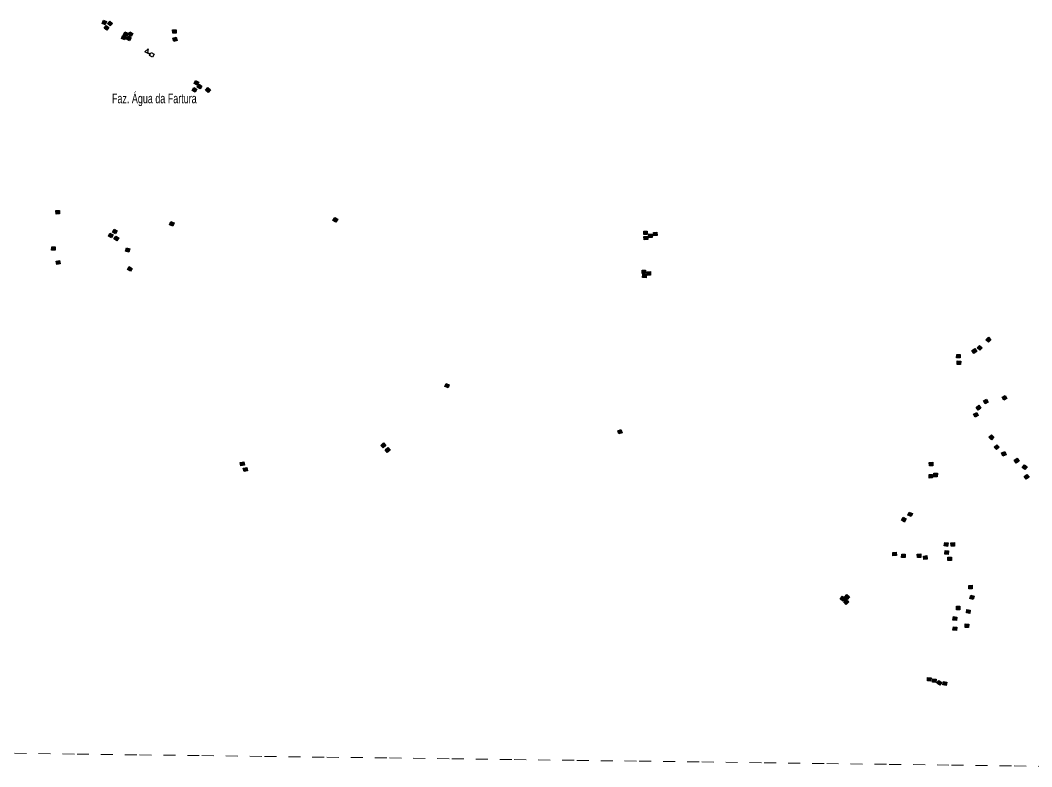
# Model space of a CAD drawing. Extents: x 679 to 705, y 7427.4 to 7455.4.
# Drawn here: x 683.78 to 692.24, y 7427.52 to 7433.76 of the extents above; entities that cross this region are included whole.
import ezdxf

# ---------------------------------------------------------------- set-up
doc = ezdxf.new("R2010")
doc.units = 0
doc.header["$LTSCALE"] = 0.032
doc.linetypes.add('SHORT_DASHED', pattern=[2.7, 1.5, -1.2])
for name, color, linetype, lineweight in [('2', 7, 'Continuous', 25), ('4', 7, 'Continuous', 25), ('58', 7, 'SHORT_DASHED', 13)]:
    doc.layers.add(name, color=color, linetype=linetype, lineweight=lineweight)
doc.layers.add('61', color=7, linetype='Continuous')

msp = doc.modelspace()

# ---------------------------------------------------------------- hatches: boundary and pattern name
at = {"layer": '2'}
for points in [[(684.5058, 7433.7514), (684.4944, 7433.7248), (684.4678, 7433.7362), (684.4792, 7433.7628)], [(684.5551, 7433.7368), (684.5357, 7433.7153), (684.5141, 7433.7347), (684.5335, 7433.7562)], [(684.5253, 7433.7023), (684.5082, 7433.6788), (684.4848, 7433.6959), (684.5019, 7433.7193)], [(684.6858, 7433.6543), (684.6741, 7433.6277), (684.6476, 7433.6393), (684.6592, 7433.6659)], [(684.7242, 7433.6515), (684.7106, 7433.6259), (684.685, 7433.6395), (684.6986, 7433.6651)], [(685.0861, 7433.6838), (685.087, 7433.6548), (685.058, 7433.6539), (685.0571, 7433.6829)], [(684.6678, 7433.6238), (684.6549, 7433.5979), (684.6289, 7433.6109), (684.6419, 7433.6368)], [(684.7103, 7433.6159), (684.6961, 7433.5906), (684.6708, 7433.6049), (684.685, 7433.6301)], [(685.0876, 7433.622), (685.096, 7433.5942), (685.0682, 7433.5859), (685.0598, 7433.6136)], [(685.2755, 7433.2451), (685.2622, 7433.2193), (685.2364, 7433.2326), (685.2497, 7433.2584)], [(685.3027, 7433.2123), (685.2869, 7433.188), (685.2626, 7433.2038), (685.2784, 7433.2281)], [(685.2603, 7433.1851), (685.2458, 7433.1601), (685.2207, 7433.1746), (685.2353, 7433.1997)], [(685.3514, 7433.2006), (685.3729, 7433.1812), (685.3535, 7433.1597), (685.332, 7433.1791)], [(684.1105, 7432.172), (684.1117, 7432.1431), (684.0827, 7432.1419), (684.0816, 7432.1709)], [(685.0432, 7432.08), (685.0697, 7432.0682), (685.0578, 7432.0417), (685.0314, 7432.0535)], [(686.4118, 7432.113), (686.437, 7432.0985), (686.4225, 7432.0734), (686.3973, 7432.0879)], [(684.5333, 7431.983), (684.5592, 7431.97), (684.5463, 7431.9441), (684.5203, 7431.9571)], [(684.5681, 7432.0157), (684.5932, 7432.0012), (684.5788, 7431.9761), (684.5536, 7431.9905)], [(684.5833, 7431.9583), (684.6075, 7431.9423), (684.5915, 7431.9181), (684.5673, 7431.9341)], [(689.0243, 7431.9993), (689.0235, 7431.9703), (688.9945, 7431.9712), (688.9953, 7432.0002)], [(689.0254, 7431.9587), (689.0281, 7431.9298), (688.9992, 7431.9271), (688.9965, 7431.956)], [(689.0652, 7431.9753), (689.0641, 7431.9463), (689.0351, 7431.9474), (689.0362, 7431.9764)], [(689.1042, 7431.9909), (689.1066, 7431.962), (689.0777, 7431.9596), (689.0753, 7431.9885)], [(684.0761, 7431.8682), (684.0747, 7431.8393), (684.0457, 7431.8407), (684.0472, 7431.8697)], [(684.6721, 7431.8593), (684.6999, 7431.8511), (684.6917, 7431.8233), (684.6639, 7431.8314)], [(684.1124, 7431.7542), (684.117, 7431.7256), (684.0884, 7431.721), (684.0838, 7431.7496)], [(684.6954, 7431.7038), (684.7199, 7431.6882), (684.7043, 7431.6637), (684.6798, 7431.6793)], [(689.0099, 7431.6735), (689.0099, 7431.6445), (688.9809, 7431.6445), (688.9809, 7431.6735)], [(689.0166, 7431.6372), (689.0142, 7431.6083), (688.9853, 7431.6107), (688.9877, 7431.6396)], [(689.0497, 7431.6617), (689.0516, 7431.6328), (689.0226, 7431.6309), (689.0208, 7431.6598)], [(691.8751, 7431.112), (691.8956, 7431.0914), (691.8751, 7431.0709), (691.8546, 7431.0915)], [(691.8016, 7431.0445), (691.8226, 7431.0245), (691.8026, 7431.0035), (691.7816, 7431.0235)], [(691.6393, 7430.9682), (691.6382, 7430.9392), (691.6093, 7430.9403), (691.6103, 7430.9692)], [(691.7609, 7431.0174), (691.777, 7430.9933), (691.7528, 7430.9772), (691.7368, 7431.0014)], [(691.6435, 7430.9134), (691.6424, 7430.8844), (691.6135, 7430.8855), (691.6145, 7430.9144)], [(687.3428, 7430.7265), (687.3696, 7430.7155), (687.3587, 7430.6887), (687.3318, 7430.6996)], [(692.016, 7430.6257), (692.0293, 7430.5999), (692.0035, 7430.5866), (691.9902, 7430.6124)], [(691.795, 7430.5438), (691.8123, 7430.5206), (691.7891, 7430.5032), (691.7718, 7430.5265)], [(691.8588, 7430.5941), (691.873, 7430.5689), (691.8477, 7430.5546), (691.8335, 7430.5799)], [(691.7771, 7430.4838), (691.7902, 7430.458), (691.7644, 7430.4449), (691.7512, 7430.4707)], [(688.8038, 7430.3414), (688.8143, 7430.3144), (688.7873, 7430.3038), (688.7768, 7430.3308)], [(691.9001, 7430.2963), (691.9206, 7430.2758), (691.9001, 7430.2553), (691.8796, 7430.2758)], [(686.8188, 7430.2286), (686.8386, 7430.2075), (686.8174, 7430.1876), (686.7976, 7430.2088)], [(686.8565, 7430.1904), (686.8743, 7430.1675), (686.8514, 7430.1497), (686.8336, 7430.1726)], [(691.9454, 7430.2138), (691.9649, 7430.1924), (691.9436, 7430.1728), (691.924, 7430.1942)], [(692.0112, 7430.1574), (692.0223, 7430.1306), (691.9955, 7430.1195), (691.9844, 7430.1463)], [(692.1148, 7430.1014), (692.1316, 7430.0778), (692.108, 7430.061), (692.0912, 7430.0846)], [(685.6515, 7430.0709), (685.6569, 7430.0425), (685.6285, 7430.037), (685.623, 7430.0655)], [(685.6764, 7430.0247), (685.6827, 7429.9964), (685.6544, 7429.9901), (685.6481, 7430.0184)], [(691.4092, 7430.0677), (691.4118, 7430.0388), (691.3829, 7430.0362), (691.3803, 7430.0651)], [(692.1755, 7430.0465), (692.1977, 7430.0278), (692.179, 7430.0056), (692.1568, 7430.0243)], [(691.4078, 7429.9654), (691.4089, 7429.9364), (691.3799, 7429.9354), (691.3788, 7429.9643)], [(691.4489, 7429.9752), (691.4481, 7429.9462), (691.4191, 7429.9469), (691.4199, 7429.9759)], [(692.1967, 7429.966), (692.2143, 7429.943), (692.1912, 7429.9254), (692.1736, 7429.9484)], [(691.1626, 7429.6074), (691.1878, 7429.5931), (691.1735, 7429.5678), (691.1483, 7429.5822)], [(691.214, 7429.6513), (691.2403, 7429.6391), (691.2281, 7429.6128), (691.2018, 7429.6251)], [(691.5383, 7429.3931), (691.534, 7429.3644), (691.5053, 7429.3687), (691.5096, 7429.3974)], [(691.5905, 7429.3961), (691.5923, 7429.3672), (691.5634, 7429.3653), (691.5615, 7429.3943)], [(691.1041, 7429.3155), (691.1057, 7429.2866), (691.0767, 7429.285), (691.0752, 7429.314)], [(691.1791, 7429.2999), (691.1788, 7429.2709), (691.1498, 7429.2712), (691.1501, 7429.3002)], [(691.3093, 7429.3008), (691.3109, 7429.2718), (691.2819, 7429.2702), (691.2803, 7429.2991)], [(691.3615, 7429.2865), (691.3644, 7429.2577), (691.3356, 7429.2547), (691.3326, 7429.2835)], [(691.5418, 7429.3263), (691.5393, 7429.2974), (691.5104, 7429.2999), (691.5129, 7429.3288)], [(691.566, 7429.2746), (691.566, 7429.2456), (691.537, 7429.2456), (691.537, 7429.2746)], [(691.7391, 7429.0388), (691.7396, 7429.0098), (691.7106, 7429.0093), (691.7101, 7429.0383)], [(690.6569, 7428.9475), (690.6783, 7428.9279), (690.6587, 7428.9065), (690.6373, 7428.926)], [(690.6874, 7428.92), (690.7079, 7428.8995), (690.6874, 7428.879), (690.6669, 7428.8995)], [(690.692, 7428.9622), (690.7142, 7428.9436), (690.6956, 7428.9213), (690.6734, 7428.94)], [(691.757, 7428.9481), (691.7486, 7428.9203), (691.7208, 7428.9287), (691.7292, 7428.9565)], [(691.6362, 7428.8637), (691.6362, 7428.8347), (691.6072, 7428.8347), (691.6072, 7428.8637)], [(691.7236, 7428.832), (691.7195, 7428.8033), (691.6908, 7428.8074), (691.6949, 7428.8361)], [(691.6113, 7428.773), (691.6077, 7428.7442), (691.5789, 7428.7478), (691.5825, 7428.7766)], [(691.6115, 7428.6882), (691.6074, 7428.6595), (691.5787, 7428.6636), (691.5828, 7428.6923)], [(691.7105, 7428.7151), (691.7099, 7428.6861), (691.6809, 7428.6868), (691.6815, 7428.7158)], [(691.3961, 7428.2656), (691.3936, 7428.2367), (691.3647, 7428.2392), (691.3672, 7428.2681)], [(691.4383, 7428.2551), (691.436, 7428.2262), (691.4071, 7428.2286), (691.4094, 7428.2575)], [(691.4851, 7428.2269), (691.4684, 7428.2032), (691.4447, 7428.2199), (691.4613, 7428.2436)], [(691.5284, 7428.2302), (691.523, 7428.2017), (691.4945, 7428.2072), (691.5, 7428.2357)]]:
    msp.add_hatch(color=256, dxfattribs=at).paths.add_polyline_path(points)

# ---------------------------------------------------------------- linework, layer by layer
for points in [[(684.5058, 7433.7514), (684.4944, 7433.7248), (684.4678, 7433.7362), (684.4792, 7433.7628)], [(684.5551, 7433.7368), (684.5357, 7433.7153), (684.5141, 7433.7347), (684.5335, 7433.7562)], [(684.5253, 7433.7023), (684.5082, 7433.6788), (684.4848, 7433.6959), (684.5019, 7433.7193)], [(684.6858, 7433.6543), (684.6741, 7433.6277), (684.6476, 7433.6393), (684.6592, 7433.6659)], [(684.7242, 7433.6515), (684.7106, 7433.6259), (684.685, 7433.6395), (684.6986, 7433.6651)], [(685.0861, 7433.6838), (685.087, 7433.6548), (685.058, 7433.6539), (685.0571, 7433.6829)], [(684.6678, 7433.6238), (684.6549, 7433.5979), (684.6289, 7433.6109), (684.6419, 7433.6368)], [(684.7103, 7433.6159), (684.6961, 7433.5906), (684.6708, 7433.6049), (684.685, 7433.6301)], [(685.0876, 7433.622), (685.096, 7433.5942), (685.0682, 7433.5859), (685.0598, 7433.6136)], [(685.2755, 7433.2451), (685.2622, 7433.2193), (685.2364, 7433.2326), (685.2497, 7433.2584)], [(685.3027, 7433.2123), (685.2869, 7433.188), (685.2626, 7433.2038), (685.2784, 7433.2281)], [(685.2603, 7433.1851), (685.2458, 7433.1601), (685.2207, 7433.1746), (685.2353, 7433.1997)], [(685.3514, 7433.2006), (685.3729, 7433.1812), (685.3535, 7433.1597), (685.332, 7433.1791)], [(684.1105, 7432.172), (684.1117, 7432.1431), (684.0827, 7432.1419), (684.0816, 7432.1709)], [(685.0432, 7432.08), (685.0697, 7432.0682), (685.0578, 7432.0417), (685.0314, 7432.0535)], [(686.4118, 7432.113), (686.437, 7432.0985), (686.4225, 7432.0734), (686.3973, 7432.0879)], [(684.5333, 7431.983), (684.5592, 7431.97), (684.5463, 7431.9441), (684.5203, 7431.9571)], [(684.5681, 7432.0157), (684.5932, 7432.0012), (684.5788, 7431.9761), (684.5536, 7431.9905)], [(684.5833, 7431.9583), (684.6075, 7431.9423), (684.5915, 7431.9181), (684.5673, 7431.9341)], [(689.0243, 7431.9993), (689.0235, 7431.9703), (688.9945, 7431.9712), (688.9953, 7432.0002)], [(689.0254, 7431.9587), (689.0281, 7431.9298), (688.9992, 7431.9271), (688.9965, 7431.956)], [(689.0652, 7431.9753), (689.0641, 7431.9463), (689.0351, 7431.9474), (689.0362, 7431.9764)], [(689.1042, 7431.9909), (689.1066, 7431.962), (689.0777, 7431.9596), (689.0753, 7431.9885)], [(684.0761, 7431.8682), (684.0747, 7431.8393), (684.0457, 7431.8407), (684.0472, 7431.8697)], [(684.6721, 7431.8593), (684.6999, 7431.8511), (684.6917, 7431.8233), (684.6639, 7431.8314)], [(684.1124, 7431.7542), (684.117, 7431.7256), (684.0884, 7431.721), (684.0838, 7431.7496)], [(684.6954, 7431.7038), (684.7199, 7431.6882), (684.7043, 7431.6637), (684.6798, 7431.6793)], [(689.0099, 7431.6735), (689.0099, 7431.6445), (688.9809, 7431.6445), (688.9809, 7431.6735)], [(689.0166, 7431.6372), (689.0142, 7431.6083), (688.9853, 7431.6107), (688.9877, 7431.6396)], [(689.0497, 7431.6617), (689.0516, 7431.6328), (689.0226, 7431.6309), (689.0208, 7431.6598)], [(691.8751, 7431.112), (691.8956, 7431.0914), (691.8751, 7431.0709), (691.8546, 7431.0915)], [(691.8016, 7431.0445), (691.8226, 7431.0245), (691.8026, 7431.0035), (691.7816, 7431.0235)], [(691.6393, 7430.9682), (691.6382, 7430.9392), (691.6093, 7430.9403), (691.6103, 7430.9692)], [(691.7609, 7431.0174), (691.777, 7430.9933), (691.7528, 7430.9772), (691.7368, 7431.0014)], [(691.6435, 7430.9134), (691.6424, 7430.8844), (691.6135, 7430.8855), (691.6145, 7430.9144)], [(687.3428, 7430.7265), (687.3696, 7430.7155), (687.3587, 7430.6887), (687.3318, 7430.6996)], [(692.016, 7430.6257), (692.0293, 7430.5999), (692.0035, 7430.5866), (691.9902, 7430.6124)], [(691.795, 7430.5438), (691.8123, 7430.5206), (691.7891, 7430.5032), (691.7718, 7430.5265)], [(691.8588, 7430.5941), (691.873, 7430.5689), (691.8477, 7430.5546), (691.8335, 7430.5799)], [(691.7771, 7430.4838), (691.7902, 7430.458), (691.7644, 7430.4449), (691.7512, 7430.4707)], [(688.8038, 7430.3414), (688.8143, 7430.3144), (688.7873, 7430.3038), (688.7768, 7430.3308)], [(691.9001, 7430.2963), (691.9206, 7430.2758), (691.9001, 7430.2553), (691.8796, 7430.2758)], [(686.8188, 7430.2286), (686.8386, 7430.2075), (686.8174, 7430.1876), (686.7976, 7430.2088)], [(686.8565, 7430.1904), (686.8743, 7430.1675), (686.8514, 7430.1497), (686.8336, 7430.1726)], [(691.9454, 7430.2138), (691.9649, 7430.1924), (691.9436, 7430.1728), (691.924, 7430.1942)], [(692.0112, 7430.1574), (692.0223, 7430.1306), (691.9955, 7430.1195), (691.9844, 7430.1463)], [(692.1148, 7430.1014), (692.1316, 7430.0778), (692.108, 7430.061), (692.0912, 7430.0846)], [(685.6515, 7430.0709), (685.6569, 7430.0425), (685.6285, 7430.037), (685.623, 7430.0655)], [(685.6764, 7430.0247), (685.6827, 7429.9964), (685.6544, 7429.9901), (685.6481, 7430.0184)], [(691.4092, 7430.0677), (691.4118, 7430.0388), (691.3829, 7430.0362), (691.3803, 7430.0651)], [(692.1755, 7430.0465), (692.1977, 7430.0278), (692.179, 7430.0056), (692.1568, 7430.0243)], [(691.4078, 7429.9654), (691.4089, 7429.9364), (691.3799, 7429.9354), (691.3788, 7429.9643)], [(691.4489, 7429.9752), (691.4481, 7429.9462), (691.4191, 7429.9469), (691.4199, 7429.9759)], [(692.1967, 7429.966), (692.2143, 7429.943), (692.1912, 7429.9254), (692.1736, 7429.9484)], [(691.1626, 7429.6074), (691.1878, 7429.5931), (691.1735, 7429.5678), (691.1483, 7429.5822)], [(691.214, 7429.6513), (691.2403, 7429.6391), (691.2281, 7429.6128), (691.2018, 7429.6251)], [(691.5383, 7429.3931), (691.534, 7429.3644), (691.5053, 7429.3687), (691.5096, 7429.3974)], [(691.5905, 7429.3961), (691.5923, 7429.3672), (691.5634, 7429.3653), (691.5615, 7429.3943)], [(691.1041, 7429.3155), (691.1057, 7429.2866), (691.0767, 7429.285), (691.0752, 7429.314)], [(691.1791, 7429.2999), (691.1788, 7429.2709), (691.1498, 7429.2712), (691.1501, 7429.3002)], [(691.3093, 7429.3008), (691.3109, 7429.2718), (691.2819, 7429.2702), (691.2803, 7429.2991)], [(691.3615, 7429.2865), (691.3644, 7429.2577), (691.3356, 7429.2547), (691.3326, 7429.2835)], [(691.5418, 7429.3263), (691.5393, 7429.2974), (691.5104, 7429.2999), (691.5129, 7429.3288)], [(691.566, 7429.2746), (691.566, 7429.2456), (691.537, 7429.2456), (691.537, 7429.2746)], [(691.7391, 7429.0388), (691.7396, 7429.0098), (691.7106, 7429.0093), (691.7101, 7429.0383)], [(690.6569, 7428.9475), (690.6783, 7428.9279), (690.6587, 7428.9065), (690.6373, 7428.926)], [(690.6874, 7428.92), (690.7079, 7428.8995), (690.6874, 7428.879), (690.6669, 7428.8995)], [(690.692, 7428.9622), (690.7142, 7428.9436), (690.6956, 7428.9213), (690.6734, 7428.94)], [(691.757, 7428.9481), (691.7486, 7428.9203), (691.7208, 7428.9287), (691.7292, 7428.9565)], [(691.6362, 7428.8637), (691.6362, 7428.8347), (691.6072, 7428.8347), (691.6072, 7428.8637)], [(691.7236, 7428.832), (691.7195, 7428.8033), (691.6908, 7428.8074), (691.6949, 7428.8361)], [(691.6113, 7428.773), (691.6077, 7428.7442), (691.5789, 7428.7478), (691.5825, 7428.7766)], [(691.6115, 7428.6882), (691.6074, 7428.6595), (691.5787, 7428.6636), (691.5828, 7428.6923)], [(691.7105, 7428.7151), (691.7099, 7428.6861), (691.6809, 7428.6868), (691.6815, 7428.7158)], [(691.3961, 7428.2656), (691.3936, 7428.2367), (691.3647, 7428.2392), (691.3672, 7428.2681)], [(691.4383, 7428.2551), (691.436, 7428.2262), (691.4071, 7428.2286), (691.4094, 7428.2575)], [(691.4851, 7428.2269), (691.4684, 7428.2032), (691.4447, 7428.2199), (691.4613, 7428.2436)], [(691.5284, 7428.2302), (691.523, 7428.2017), (691.4945, 7428.2072), (691.5, 7428.2357)]]:
    msp.add_lwpolyline(points, close=True, dxfattribs=at)
at = {"layer": '4'}
for points in [[(684.8693, 7433.4775), (684.8262, 7433.4995), (684.852, 7433.5244), (684.8483, 7433.4937), (684.8715, 7433.4818)], [(684.8715, 7433.4818), (684.877, 7433.4926), (684.9028, 7433.4794), (684.8896, 7433.4536), (684.8638, 7433.4668), (684.8693, 7433.4775)]]:
    msp.add_lwpolyline(points, dxfattribs=at)
at = {"layer": '58'}
msp.add_lwpolyline([(683.7362, 7427.6341), (684.2583, 7427.6276), (684.7804, 7427.6212), (685.3025, 7427.6146), (685.8246, 7427.6081), (686.3467, 7427.6016), (686.8688, 7427.595), (687.3909, 7427.5884), (687.913, 7427.5818), (688.4351, 7427.5752), (688.9572, 7427.5686), (689.4793, 7427.5619), (690.0014, 7427.5552), (690.5235, 7427.5486), (691.0457, 7427.5418), (691.5678, 7427.5351), (692.0899, 7427.5284), (692.612, 7427.5216)], dxfattribs=at)

# ---------------------------------------------------------------- texts
at = {"layer": '61', "width": 0.7}
msp.add_text('Faz. Água da Fartura', height=0.08, dxfattribs=at).set_placement((684.5505, 7433.0686))

doc.saveas('drawing.dxf')
